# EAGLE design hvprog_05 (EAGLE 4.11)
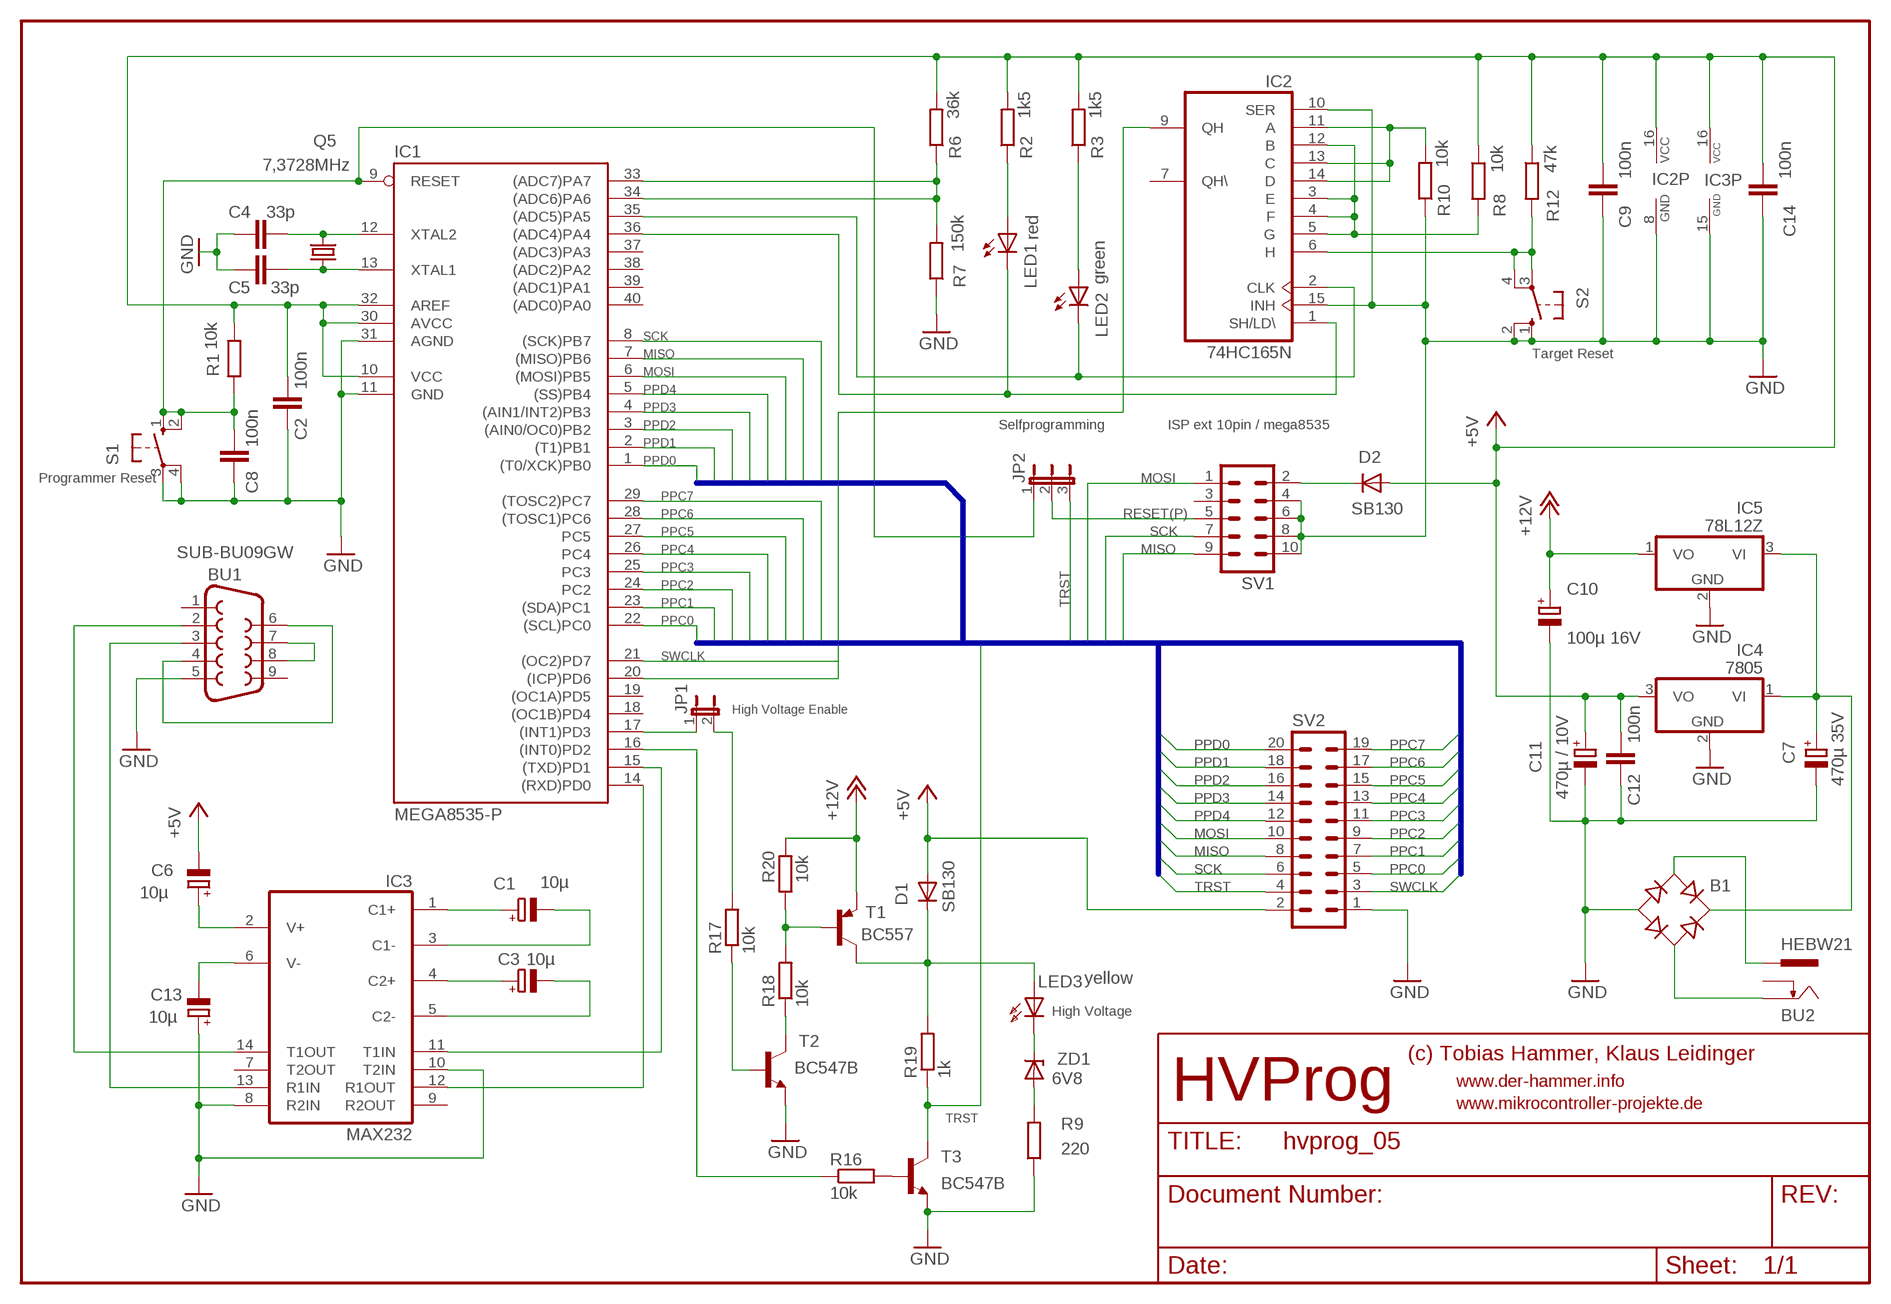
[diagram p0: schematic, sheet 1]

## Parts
B1  RB1A  [RB1A]
BU1  SUB-BU09GW  SUBD-F9WD-SUB-BU09GW  [SUBD-F9]
BU2  HEBW21  [HEBW21]
C1  10µ  CPOL-EUE1.8-4  [E1,8-4]
C2  100n  C-EU025-024X044  [C025-024X044]
C3  10µ  CPOL-EUE1.8-4  [E1,8-4]
C4  33p  C-EUC0805  [C0805]
C5  33p  C-EUC0805  [C0805]
C6  10µ  CPOL-EUE1.8-4  [E1,8-4]
C7  470µ 35V  CPOL-EUE5-10.5  [E5-10,5]
C8  100n  C-EU025-024X044  [C025-024X044]
C9  100n  C-EU025-024X044  [C025-024X044]
C10  100µ 16V  CPOL-EUE2.5-7  [E2,5-7]
C11  470µ / 10V  CPOL-EUE2.5-7  [E2,5-7]
C12  100n  C-EU025-024X044  [C025-024X044]
C13  10µ  CPOL-EUE1.8-4  [E1,8-4]
C14  100n  C-EU025-024X044  [C025-024X044]
D1  SB130  DIODE-D-2.5  [D-2.5]
D2  SB130  1N41485MM  [D-5]
IC1  MEGA8535-P  [DIL40]
IC2  74HC165N  [DIL16]
IC3  MAX232  [DIL16]
IC4  7805  78KL  [TO220H]
IC5  78L12Z  [TO92]
JP1  JP1E  [JP1]
JP2  JP2E  [JP2]
LED1  red  LED3MM  [LED3MM]
LED2  green  LED3MM  [LED3MM]
LED3  yellow  LED3MM  [LED3MM]
Q5  7,3728MHz  CRYTALHC49U-V  [HC49U-V]
R1  10k  R-EU_0204/7  [0204/7]
R2  1k5  R-EU_0204/7  [0204/7]
R3  1k5  R-EU_0204/7  [0204/7]
R6  36k  R-EU_0204/7  [0204/7]
R7  150k  R-EU_0204/7  [0204/7]
R8  10k  R-EU_0204/7  [0204/7]
R9  220  R-EU_0204/7  [0204/7]
R10  10k  R-EU_0204/7  [0204/7]
R12  47k  R-EU_0204/7  [0204/7]
R16  10k  R-EU_0204/7  [0204/7]
R17  10k  R-EU_0204/7  [0204/7]
R18  10k  R-EU_0204/7  [0204/7]
R19  1k  R-EU_0204/7  [0204/7]
R20  10k  R-EU_0204/7  [0204/7]
S1  10-XX  [B3F-10XX]
S2  10-XX  [B3F-10XX]
SV1  ML10L  [ML10L]
SV2  ML20L  [ML20L]
T1  BC557  [TO92]
T2  BC547B  [TO92]
T3  BC547B  [TO92]
ZD1  6V8  ZENER-DIODEZD-7.5  [ZDIO-7.5]

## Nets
+5V: C2.2 C6.- C9.1 C11.+ C12.1 C14.1 D1.A D2.A IC1.10(VCC) IC1.30(AVCC) IC1.32(AREF) IC2.16(VCC) IC3.16(VCC) IC4.3(VO) R1.2 R2.2 R3.2 R6.2 R8.1 R12.1 SV2.2
+12V: C10.+ IC5.1(VO) R20.2 T1.1(E)
GND: B1.- BU1.5 C2.1 C4.1 C5.1 C7.- C8.1 C9.2 C10.- C11.- C12.2 C13.+ C14.2 IC1.11(GND) IC1.31(AGND) IC2.8(GND) IC2.10(SER) IC2.15(INH) IC3.8(R2IN) IC3.10(T2IN) IC3.15(GND) IC4.2(GND) IC5.2(GND) R7.1 R9.1 R10.1 S1.3(P) S1.4(P1) S2.1(S) S2.2(S1) SV1.4 SV1.6 SV1.8 SV1.10 SV2.1 T2.1(E) T3.1(E)
MISO: IC1.7((MISO)PB6) SV1.9 SV2.8
MOSI: IC1.6((MOSI)PB5) SV1.1 SV2.10
N: IC1.36((ADC4)PA4) IC2.1(SH/LD\) LED1.K(C)
N$1: C4.2 IC1.12(XTAL2) Q5.2
N$2: C5.2 IC1.13(XTAL1) Q5.1
N$3: C8.2 IC1.9(RESET) JP2.1 R1.1 S1.1(S) S1.2(S1)
N$4: LED1.A R2.1
N$5: LED2.A R3.1
N$6: IC1.20((ICP)PD6) IC2.9(QH)
N$7: IC2.11(A) IC2.13(C) IC2.14(D) R10.2
N$8: IC1.35((ADC5)PA5) IC2.2(CLK) LED2.K(C)
N$9: IC1.33((ADC7)PA7) IC1.34((ADC6)PA6) R6.1 R7.2
N$10: BU1.7 BU1.8
N$11: IC1.16((INT0)PD2) R16.1
N$12: IC2.3(E) IC2.4(F) IC2.5(G) IC2.12(B) R8.2
N$13: R16.2 T3.2(B)
N$14: C1.+ IC3.1(C1+)
N$15: C1.- IC3.3(C1-)
N$16: C3.+ IC3.4(C2+)
N$17: C3.- IC3.5(C2-)
N$18: C13.- IC3.6(V-)
N$19: C6.+ IC3.2(V+)
N$20: IC2.6(H) R12.2 S2.3(P) S2.4(P1)
N$21: B1.+ C7.+ IC4.1(VI) IC5.3(VI)
N$22: B1.AC1 BU2.P$S(S)
N$23: B1.AC2 BU2.P$R(R)
N$24: LED3.K(C) ZD1.C
N$25: BU1.2 IC3.14(T1OUT)
N$26: BU1.3 IC3.13(R1IN)
N$27: IC1.14((RXD)PD0) IC3.12(R1OUT)
N$28: IC1.15((TXD)PD1) IC3.11(T1IN)
N$29: IC1.17((INT1)PD3) JP1.1
N$30: JP1.2 R17.2
N$31: R9.2 ZD1.A
N$32: BU1.4 BU1.6
N$33: D2.C SV1.2
N$34: D1.C LED3.A R19.2 T1.3(C)
N$35: R17.1 T2.2(B)
N$36: R18.1 T2.3(C)
N$38: R18.2 R20.1 T1.2(B)
PPC0: IC1.22((SCL)PC0) SV2.5
PPC1: IC1.23((SDA)PC1) SV2.7
PPC2: IC1.24(PC2) SV2.9
PPC3: IC1.25(PC3) SV2.11
PPC4: IC1.26(PC4) SV2.13
PPC5: IC1.27(PC5) SV2.15
PPC6: IC1.28((TOSC1)PC6) SV2.17
PPC7: IC1.29((TOSC2)PC7) SV2.19
PPD0: IC1.1((T0/XCK)PB0) SV2.20
PPD1: IC1.2((T1)PB1) SV2.18
PPD2: IC1.3((AIN0/OC0)PB2) SV2.16
PPD3: IC1.4((AIN1/INT2)PB3) SV2.14
PPD4: IC1.5((SS)PB4) SV2.12
RESET(P): JP2.2 SV1.5
SCK: IC1.8((SCK)PB7) SV1.7 SV2.6
SWCLK: IC1.21((OC2)PD7) SV2.3
TRST: JP2.3 R19.1 SV2.4 T3.3(C)
Unconnected: BU1.1 BU1.9 BU2.P$RS(RS) IC1.18((OC1B)PD4) IC1.19((OC1A)PD5) IC1.37((ADC3)PA3) IC1.38((ADC2)PA2) IC1.39((ADC1)PA1) IC1.40((ADC0)PA0) IC2.7(QH\) IC3.7(T2OUT) IC3.9(R2OUT) SV1.3

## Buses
B$2

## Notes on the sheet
- Target Reset
- Selfprogramming | ISP ext 10pin / mega8535
- Programmer Reset
- High Voltage Enable
- High Voltage
- (c) Tobias Hammer, Klaus Leidinger
- www.der-hammer.info
- HVProg
- www.mikrocontroller-projekte.de

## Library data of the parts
B1 = rectifier:RB1A: RECTIFIER 1 A
BU1 = mikrocontroller-projekte:SUBD-F9W
BU2 = mikrocontroller-projekte:HEBW21: Hohlstecker Winkelbuchse Reichelt HEBW21/25
C1 C3 C6 = rcl:CPOL-EU: POLARIZED CAPACITOR, European symbol
C2 C4 C5 C8 C9 C14 = rcl:C-EU: CAPACITOR, European symbol
C7 C10 C11 C13 = rc-elektronik:CPOL-EU: POLARIZED CAPACITOR, European symbol
C12 = rc-elektronik:C-EU: CAPACITOR, European symbol
D1 = diode:DIODE-: DIODE
D2 = diode:1N4148: DIODE
IC1 = avr:MEGA8535-P: MICROCONTROLLER 8 Kbytes FLASH 512 bytes SRAM 512 bytes EEPROM USART 8-channel 10 bit ADC
IC2 = 74xx-eu:74*165: 8-bit parallel load SHIFT REGISTER
IC3 = maxim:MAX232: RS232 TRANSEIVER
IC4 IC5 = rc-elektronik:78*: Positive VOLTAGE REGULATOR
JP1 = jumper:JP1E: JUMPER
JP2 = jumper:JP2E: JUMPER
LED1 LED2 = led:LED: LED
LED3 = rc-elektronik:LED: LED
Q5 = crystal:CRYTAL: CRYSTAL
R1-R3 R6-R10 R12 R16-R20 = rcl:R-EU_: RESISTOR, European symbol
S1 S2 = switch-omron:10-XX: OMRON SWITCH
SV1 = con-harting-ml:ML10: HARTING
SV2 = con-harting-ml:ML20: HARTING
T1 = transistor-pnp:BC557: PNP Transistor
T2 T3 = transistor-npn:BC547*: NPN Transistor
ZD1 = diode:ZENER-DIODE: Z-Diode

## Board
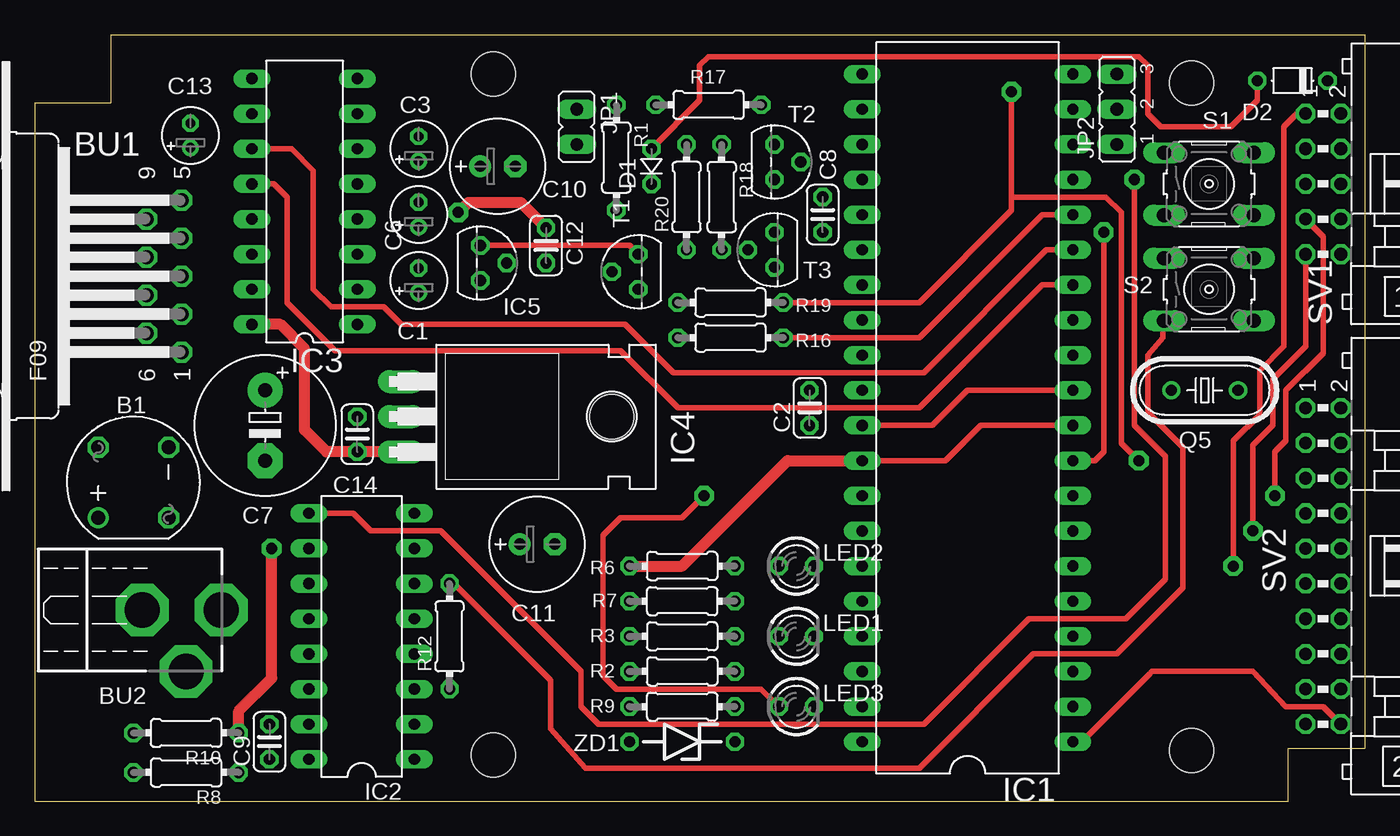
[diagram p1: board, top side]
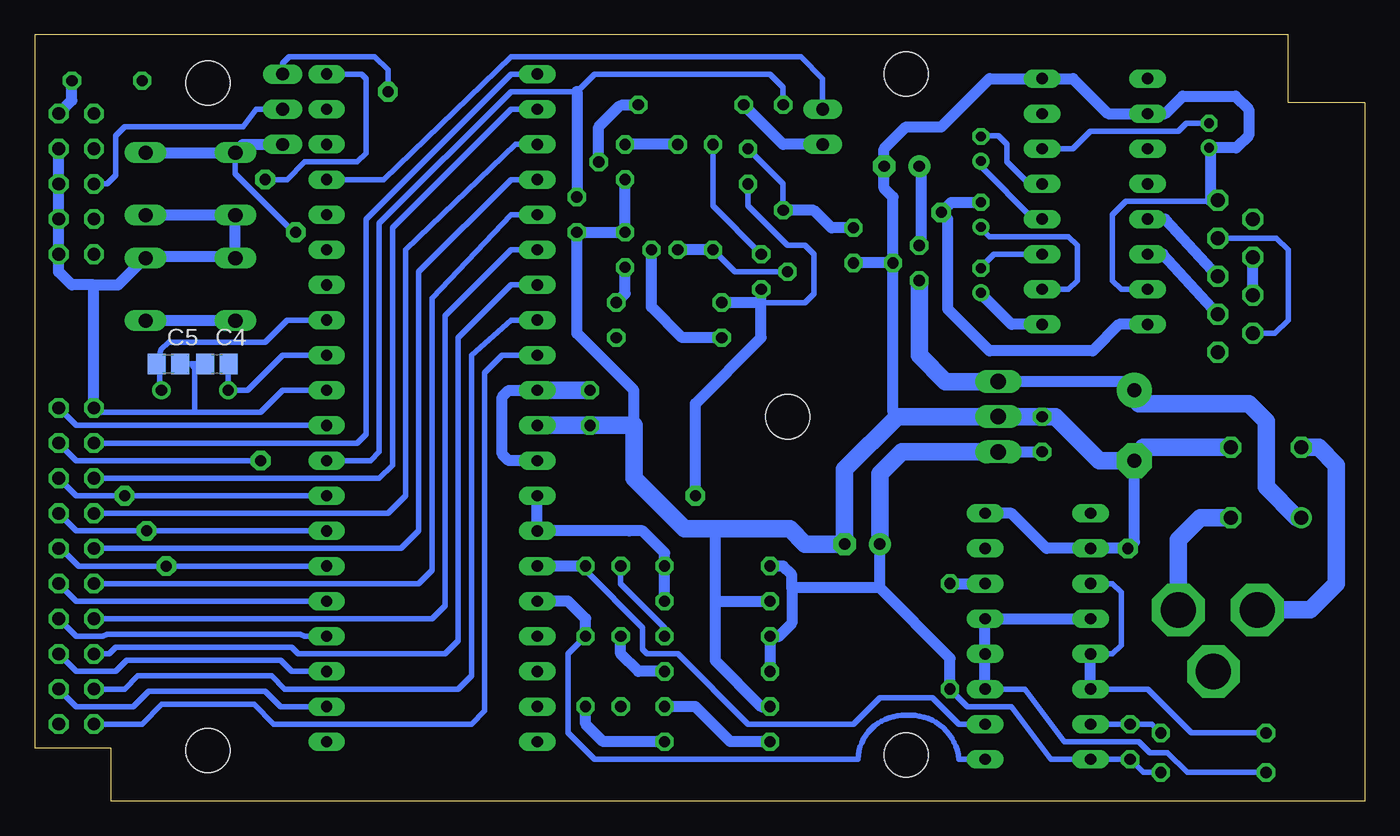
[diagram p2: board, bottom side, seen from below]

Size 96.2 x 55.4 mm. Coordinates in mm from the lower left corner, seen from the top.
Outline: 90.65,0 90.65,3.81 96.2,3.81 96.2,55.4 5.56,55.4 5.56,50.48 0,50.48 0,0 90.65,0
Copper layers (1*16): Top 0.035mm / dielectric 1.5mm / Bottom 0.035mm
Design rules "default": minimum track width 10mil, minimum drill 24mil, track to track 8mil, track to pad 8mil, pad to pad 8mil, via to via 8mil, smd to smd 8mil, copper to edge 40mil, drill to drill 8mil, minimum pad ring 10mil, minimum via ring 8mil, stop-mask expansion 4mil, vias tented up to drill 0mil, thermal gap 10mil
Holes 3.2 mm at 33.18,52.55 33.18,3.33 83.66,3.65 83.66,51.91 41.75,27.78

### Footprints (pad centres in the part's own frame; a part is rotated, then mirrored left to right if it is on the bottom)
RB1A = drill 1.016 round: + -2.54,2.54 | drill 1.016 octagon: - 2.54,-2.54; AC1 2.54,2.54; AC2 -2.54,-2.54
SUBD-F9 = drill 1.016 octagon: 1 -5.486,-10.16; 2 -2.743,-10.16; 3 0,-10.16; 4 2.743,-10.16; 5 5.486,-10.16; 6 -4.115,-7.62; 7 -1.372,-7.62; 8 1.372,-7.62; 9 4.115,-7.62
HEBW21 = drill 2.54 pad 3.81 octagon: P$R 0,3.175; P$RS 4.445,0.635; P$S 0,-2.54
E1,8-4 = drill 0.711 pad 1.168 round: + -0.889,0 | drill 0.711 pad 1.168 octagon: - 0.889,0
C025-024X044 = drill 0.813 octagon: 1 -1.27,0; 2 1.27,0
C0805 = smd 1.3 x 1.5: 1 -0.85,0; 2 0.85,0
E5-10,5 = drill 1.016 pad 2.54 round: + -2.54,0 | drill 1.016 pad 2.54 octagon: - 2.54,0
E2,5-7 = drill 0.813 pad 1.6 round: + -1.27,0 | drill 0.813 pad 1.6 octagon: - 1.27,0
D-2.5 = drill 0.813 octagon: A 1.27,0; C -1.27,0
D-5 = drill 0.813 octagon: A 2.54,0; C -2.54,0
DIL40 = drill 0.813 long: 1 -24.13,-7.62; 2 -21.59,-7.62; 3 -19.05,-7.62; 4 -16.51,-7.62; 5 -13.97,-7.62; 6 -11.43,-7.62; 7 -8.89,-7.62; 8 -6.35,-7.62; 9 -3.81,-7.62; 10 -1.27,-7.62; 11 1.27,-7.62; 12 3.81,-7.62; 13 6.35,-7.62; 14 8.89,-7.62; 15 11.43,-7.62; 16 13.97,-7.62; 17 16.51,-7.62; 18 19.05,-7.62; 19 21.59,-7.62; 20 24.13,-7.62; 21 24.13,7.62; 22 21.59,7.62; 23 19.05,7.62; 24 16.51,7.62; 25 13.97,7.62; 26 11.43,7.62; 27 8.89,7.62; 28 6.35,7.62; 29 3.81,7.62; 30 1.27,7.62; 31 -1.27,7.62; 32 -3.81,7.62; 33 -6.35,7.62; 34 -8.89,7.62; 35 -11.43,7.62; 36 -13.97,7.62; 37 -16.51,7.62; 38 -19.05,7.62; 39 -21.59,7.62; 40 -24.13,7.62
DIL16 = drill 0.813 long: 1 -8.89,-3.81; 2 -6.35,-3.81; 3 -3.81,-3.81; 4 -1.27,-3.81; 5 1.27,-3.81; 6 3.81,-3.81; 7 6.35,-3.81; 8 8.89,-3.81; 9 8.89,3.81; 10 6.35,3.81; 11 3.81,3.81; 12 1.27,3.81; 13 -1.27,3.81; 14 -3.81,3.81; 15 -6.35,3.81; 16 -8.89,3.81
TO220H = drill 1.118 long: 1 -2.54,-10.16; 2 0,-10.16; 3 2.54,-10.16
TO92 = drill 0.813 octagon: 1 -1.27,0; 2 0,1.905; 3 1.27,0
JP1 = drill 0.914 long: 1 0,-1.27; 2 0,1.27
JP2 = drill 0.914 long: 1 -2.54,0; 2 0,0; 3 2.54,0
LED3MM = drill 0.813 octagon: A -1.27,0; K 1.27,0
HC49U-V = drill 0.813 round: 1 -2.413,0; 2 2.413,0
0204/7 = drill 0.813 octagon: 1 -3.81,0; 2 3.81,0
B3F-10XX = drill 1.016 long: 1 -3.251,2.261; 2 3.251,2.261; 3 -3.251,-2.261; 4 3.251,-2.261
ML10L = drill 0.914 octagon: 1 -5.08,-1.27; 2 -5.08,1.27; 3 -2.54,-1.27; 4 -2.54,1.27; 5 0,-1.27; 6 0,1.27; 7 2.54,-1.27; 8 2.54,1.27; 9 5.08,-1.27; 10 5.08,1.27
ML20L = drill 0.914 octagon: 1 -11.43,-1.27; 2 -11.43,1.27; 3 -8.89,-1.27; 4 -8.89,1.27; 5 -6.35,-1.27; 6 -6.35,1.27; 7 -3.81,-1.27; 8 -3.81,1.27; 9 -1.27,-1.27; 10 -1.27,1.27; 11 1.27,-1.27; 12 1.27,1.27; 13 3.81,-1.27; 14 3.81,1.27; 15 6.35,-1.27; 16 6.35,1.27; 17 8.89,-1.27; 18 8.89,1.27; 19 11.43,-1.27; 20 11.43,1.27
TO92' = drill 0.813 octagon: 1 1.27,0; 2 0,1.905; 3 -1.27,0
ZDIO-7.5 = drill 0.813 octagon: A 3.81,0; C -3.81,0

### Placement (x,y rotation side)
B1  7.14,23.02 90 top
BU1  0.48,37.94 90 top
BU2  10.32,13.81 270 top
C1  27.78,37.62 90 top
C2  56.04,28.42 90 top
C3  27.78,47.15 90 top
C4  83.03,31.59 0 bottom
C5  86.52,31.59 180 bottom
C6  27.78,42.39 90 top
C7  16.67,27.15 270 top
C8  56.99,42.39 90 top
C9  16.99,4.29 90 top
C10  33.5,45.88 0 top
C11  36.35,18.57 0 top
C12  36.99,40.16 270 top
C13  11.27,48.1 90 top
C14  23.34,26.51 90 top
D1  44.61,45.88 90 top
D2  90.96,52.07 180 top
IC1  67.47,28.42 90 top
IC2  23.65,11.91 90 top
IC3  19.53,43.34 90 top
IC4  36.67,27.78 270 top
IC5  32.23,38.89 270 top
JP1  39.21,48.74 180 top
JP2  78.26,50.01 90 top
LED1  55.09,11.91 0 top
LED2  55.09,16.99 0 top
LED3  55.09,6.83 0 top
Q5  84.61,29.69 180 top
R1  42.07,46.51 270 top
R2  46.83,9.37 180 top
R3  46.83,11.91 180 top
R6  46.83,16.99 180 top
R7  46.83,14.45 0 top
R8  10.95,2.06 180 top
R9  46.83,6.83 0 top
R10  10.95,4.92 180 top
R12  30,11.91 90 top
R16  50.32,33.5 180 top
R17  48.74,50.32 180 top
R18  49.69,43.66 270 top
R19  50.32,36.04 180 top
R20  47.15,43.66 90 top
S1  84.93,44.61 0 top
S2  84.93,36.99 0 top
SV1  93.19,44.61 270 top
SV2  93.19,16.99 270 top
T1  BC557  [TO92']  43.66,38.26 90 top
T2  BC547B  [TO92']  53.5,46.2 270 top
T3  BC547B  [TO92']  53.5,39.85 90 top
ZD1  46.83,4.29 180 top

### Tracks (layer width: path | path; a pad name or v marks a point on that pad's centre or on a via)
+5V  (via drill 0.8 pad 1.42)
  Top 0.406: IC1.10 68.42,27.15 65.88,24.61 IC1.32 | D1.A 48.1,50.64 48.1,53.18 48.74,53.82 79.85,53.82 80.49,53.18 80.49,49.69 81.44,48.74 86.52,48.74 88.42,50.64 D2.A
  Top 0.813: IC3.16 17.78,34.45 19.53,32.7 19.53,26.83 21.11,25.24 IC4.3 | C12.1 35.15,43.27 31.37,43.27 v30.64,42.55 | R6.2 46.83,16.99 54.45,24.61 IC1.32 | IC1.32 | IC4.3 | v30.64,42.55 | v30.64,42.55
  Bottom 0.406: R12.1 28.73,6.83 25.56,6.83 22.7,3.02 IC2.16 C9.1 16.03,2.06 R8.1 | IC1.10 93.19,27.15 SV2.2 | R1.2 42.07,44.61 D1.A
  Bottom 0.813: R2.2 R3.2 42.39,11.91 41.43,12.86 41.43,15.4 | 35.08,15.4 C11.+ | 35.08,15.4 41.43,15.4 | 41.43,15.4 41.43,16.35 42.07,16.99 R6.2 | R12.1 30,10.32 35.08,15.4 | C12.1 38.58,41.43 39.85,42.7 R1.2 | IC3.16 15.56,34.45 17.78,34.45 19.68,32.54 27.15,32.54 30.16,35.56 30.16,42.07 v30.64,42.55 | IC1.30 61.91,29.69 62.39,29.21 62.39,25.08 61.91,24.61 60.01,24.61 59.85,24.45 IC1.32 | IC4.3 26.67,25.24 | IC4.3 | C14.1 | IC4.3 C14.1 | v30.64,42.55 | C6.- 29.91,43.27 v30.64,42.55
  Bottom 1.27: IC1.30 C2.2 | IC4.3 33.5,25.24 35.08,23.65 C11.+
+12V
  Top 0.406: T1.1 43.02,40.16 IC5.1 | IC5.1
  Bottom 0.406: T1.1 47.15,43.02 R20.2
  Bottom 0.813: 32.07,40.01 | IC5.1 32.07,40.01 | C10.+ 32.07,45.72 32.07,40.01
GND  (via drill 0.8 pad 1.42)
  Top 0.406: IC1.11 67.47,29.69 64.93,27.15 IC1.31
  Top 0.813: R10.1 14.76,6.51 17.14,8.89 v17.14,18.26
  Bottom 0.406: S2.2 88.06,39.37 | 81.72,39.25 81.68,39.29 | 81.72,39.25 81.76,39.21 81.91,39.37 | 81.72,39.25 S2.1 | IC1.11 78.26,29.69 79.85,28.1 84.61,28.1 | R10.1 15.4,5.56 C9.2 IC2.15 | 84.61,28.1 91.6,28.1 SV2.1 | C4.1 C5.1 84.93,31.59 84.61,31.27 84.61,28.1 | IC3.15 17.62,36.99 18.26,37.62 18.26,42.39 17.3,43.34 11.27,43.34 11.18,43.43 BU1.5 | C13.+ 11.27,47.15 11.18,47.06 | 16.03,24.92 16.03,25.56 | 33.81,27.78 34.13,28.1
  Bottom 0.813: T2.1 T3.1 C8.1 56.99,33.81 52.86,29.69 52.86,26.99 | SV1.4 SV1.6 SV1.8 SV1.10 94.46,38.26 93.5,37.31 91.92,37.31 | 81.68,39.29 S1.3 81.64,42.35 | 88.06,39.37 81.91,39.37 | R9.1 43.66,6.83 46.99,10.16 46.99,14.45 | 11.18,47.06 11.18,43.43 | C13.+ 9.3,47.21 8.41,48.1 8.41,50.01 9.37,50.96 13.18,50.96 14.45,49.69 IC3.10 18.57,49.69 21.11,52.23 IC3.8 27.15,52.23 30.64,48.74 33.18,48.74 34.77,47.15 C10.- 34.77,44.29 34.13,43.66 IC5.2 | 16.03,24.92 16.35,24.29 C7.- | IC2.8 25.56,20.8 23.02,18.26 IC2.10 v17.14,18.26 | IC5.2 C12.2 | 34.13,28.1 IC5.2 | 42.86,14.45 R7.1 | 46.99,14.45 42.86,14.45 | 42.86,14.45 | 46.99,19.68 46.99,14.45 | 81.64,42.35 S1.4 | 81.64,42.35 81.6,42.39 | S2.2 88.23,39.25 90.17,37.31 91.92,37.31 | SV2.1 91.92,37.31 | v17.14,18.26 | C7.- | v17.14,18.26 16.67,18.73 C7.-
  Bottom 1.27: C2.1 IC1.31 | 16.03,25.56 B1.- | C7.- 19.21,24.61 22.38,27.78 C14.2 IC4.2 33.81,27.78 37.62,23.97 C11.- 40.48,18.57 41.59,19.68 46.99,19.68 49.21,19.68 52.86,23.34 52.86,26.99 52.86,27.15 C2.1 | C2.1
MISO  (via drill 0.8 pad 1.42)
  Top 0.406: SV1.9 91.92,32.86 89.53,30.48 89.53,27.15 88.11,25.72 v88.11,19.53
  Bottom 0.406: IC1.7 | IC1.7 v88.11,19.53 93.19,19.53 SV2.8
MOSI  (via drill 0.8 pad 1.42)
  Top 0.406: SV1.1 91.28,49.69 90.33,48.74 90.33,32.86 88.58,31.11 88.58,27.94 86.68,26.04 v86.68,16.99
  Bottom 0.406: IC1.6 | IC1.6 88.26,16.99 | SV2.10 94.3,18.26 93.03,16.99 88.26,16.99 | 88.26,16.99 v86.68,16.99
N
  Bottom 0.406: 56.36,11.59 LED1.K 57.63,10.64 57.63,4.92 55.72,3.02 36.67,3.02 arc90 33.18,6.19 arc90 29.37,3.02 IC2.1
  Bottom 0.813: IC1.36 57.63,14.45 56.36,13.18 LED1.K
N$1
  Bottom 0.406: IC1.12 78.26,32.23 80.8,29.69 Q5.2 82.2,31.46 82.07,31.59 C4.2
N$2
  Bottom 0.406: IC1.13 77.95,34.77 79.53,33.18 86.52,33.18 87.05,32.65 C5.2 87.15,31.59 87.15,29.69 Q5.1
N$3  (via drill 0.8 pad 1.42)
  Top 0.406: v77.31,41.12 77.31,25.24 76.68,24.61 IC1.9
  Bottom 0.406: IC1.9 71.91,24.61 71.28,25.24 71.28,41.75 61.75,51.28 56.99,51.28 55.72,52.55 43.02,52.55 42.07,51.59 R1.1 | 81.76,46.83 81.72,46.87 S1.1 81.68,45.33 77.47,41.12 v77.31,41.12 | 88.11,46.83 88.14,46.87 S1.2
  Bottom 0.813: JP2.1 81.12,47.47 81.72,46.87 | 81.76,46.83 88.11,46.83 | 56.99,51.28 C8.2
N$4
  Bottom 0.813: LED1.A 53.82,10.64 52.55,9.37 R2.1
N$5
  Bottom 0.406: LED2.A 53.82,15.72 50.64,12.54 R3.1
N$6  (via drill 0.8 pad 1.42)
  Top 0.406: v79.53,44.93 79.53,27.15 81.76,24.92 81.76,23.97 81.76,22.7 81.76,16.03 78.9,13.18 71.91,13.18 64.29,5.56 40.8,5.56 39.53,6.83 39.53,9.37 29.37,19.53 24.29,19.53 23.02,20.8 IC2.9
  Bottom 0.406: IC1.20 72.55,52.55 72.23,52.23 72.23,46.83 72.87,46.2 76.68,46.2 77.95,44.93 v79.53,44.93
N$7
  Bottom 0.406: R10.2 12.54,4.92 15.72,8.1 IC2.14 | IC2.11 18.26,15.72 17.62,15.08 17.62,11.27 18.26,10.64 IC2.13
  Bottom 0.813: IC2.14 IC2.13
N$8
  Bottom 0.406: LED2.K 56.36,16.67 52.23,12.54 52.23,10.95 51.91,10.64 49.69,10.64 44.61,5.56 36.99,5.56 35.08,7.46 31.27,7.46 29.37,5.56 IC2.2
  Bottom 0.813: LED2.K IC1.35
N$9
  Bottom 0.406: R6.1 50.96,16.99
  Bottom 0.813: R7.2 R6.1 50.64,17.94 52.23,19.53 53.18,19.53 IC1.34 IC1.33
N$10
  Bottom 0.813: BU1.7 BU1.8
N$11
  Top 0.406: R16.1 63.98,33.5 72.87,42.39 IC1.16
N$12
  Bottom 0.406: R8.2 12.86,2.06 14.29,3.49 15.56,3.49 16.35,4.29 21.75,4.29 24.61,8.1 IC2.3
  Bottom 0.813: IC2.3 IC2.4 IC2.5 IC2.12
N$13
  Bottom 0.813: R16.2 49.37,33.5 51.59,35.72 T3.2
N$14
  Bottom 0.406: 27.78,36.67 C1.+
  Bottom 0.813: IC3.1 25.56,34.45 27.78,36.67
N$15
  Bottom 0.406: C1.- 27.78,38.58 26.83,39.53 IC3.3
N$16
  Bottom 0.406: C3.+ 27.78,45.88 23.97,42.07 IC3.4
N$17
  Bottom 0.406: IC3.5 24.29,44.61 25.88,46.2 25.88,47.47 26.51,48.1 27.46,48.1 27.53,48.04 C3.-
N$18
  Bottom 0.406: C13.- 12.92,48.99 13.49,48.42 19.84,48.42 21.11,47.15 IC3.6
N$19
  Bottom 0.406: IC3.2 21.43,36.99 20.8,37.62 20.8,40.16 21.43,40.8 27.15,40.8 27.78,41.43 C6.+
N$20
  Top 0.406: R12.2 30,16.03 37.31,8.73 37.31,5.24 39.85,2.38 63.98,2.38 72.23,10.64 78.26,10.64 83.03,15.4 83.03,25.56 80.49,28.1 80.49,32.23 81.6,33.5 81.6,34.77
  Top 0.813: 81.6,34.77 81.64,34.73 S2.3
  Bottom 0.813: R12.2 IC2.6 | S2.4 88.14,34.73 88.11,34.77 88.07,34.73 S2.3
N$21
  Bottom 0.406: B1.+ 4.92,20.48 | C7.+ 16.67,29.37 16.35,29.05 16.35,28.73
  Bottom 0.813: C7.+ 17.3,30.32 IC4.1
  Bottom 1.27: 4.92,20.48 7.14,22.7 7.14,27.46 8.41,28.73 16.35,28.73 | IC4.1 30.32,30.32 32.23,32.23 IC5.3
N$22
  Bottom 0.406: BU2.P$S 7.78,13.49 7.46,13.81
  Bottom 1.27: B1.AC1 3.33,25.56 2.06,24.29 2.06,15.72 3.97,13.81 7.46,13.81
N$23
  Bottom 1.27: B1.AC2 11.91,20.48 13.49,18.89 BU2.P$R
N$24
  Bottom 0.813: ZD1.C 55.09,4.29 56.36,5.56 LED3.K | LED3.K
N$25
  Bottom 0.813: BU1.2 14.6,39.53 15.56,39.53 IC3.14
N$26
  Bottom 0.813: BU1.3 14.45,42.07 15.56,42.07 IC3.13
N$27
  Top 0.406: IC1.14 72.87,37.31 63.98,28.42 46.51,28.42 42.39,32.54 21.75,32.54 18.26,36.04 18.26,43.66 17.3,44.61 IC3.12
N$28
  Top 0.406: IC1.15 73.18,39.85 64.29,30.96 46.2,30.96 42.7,34.45 26.51,34.45 25.24,35.72 21.43,35.72 20.16,36.99 20.16,45.56 18.57,47.15 IC3.11
N$29
  Bottom 0.406: IC1.17 70.96,44.93 61.75,53.82 40.8,53.82 39.21,52.23 JP1.1
N$30
  Bottom 0.813: JP1.2 42.07,47.47 R17.2
N$31
  Bottom 0.813: ZD1.A 45.88,4.29 48.42,6.83 R9.2
N$32
  Bottom 0.406: BU1.4 6.39,40.68 5.56,39.85 5.56,34.77 6.51,33.81 7.94,33.81 7.95,33.83 BU1.6
N$33
  Bottom 0.813: D2.C 93.5,50.64 SV1.2
N$34  (via drill 0.8 pad 1.42)
  Top 0.406: v48.42,22.07 46.83,20.48 42.39,20.48 41.12,19.21 41.12,9.05 42.07,8.1 52.55,8.1 LED3.A
  Bottom 0.406: D1.C 44.61,43.02 41.75,40.16 40.48,40.16 39.85,39.53 39.85,36.67 40.48,36.04 43.66,36.04
  Bottom 0.813: 43.66,36.04 43.66,33.5 48.42,28.73 v48.42,22.07 | 43.66,36.04 T1.3 | 43.66,36.04 R19.2
N$35
  Bottom 0.406: 53.89,50.25 arc45 53.71,50.32
  Bottom 0.813: 53.71,50.32 R17.1 | 53.89,50.25 55.4,48.74 T2.2
N$36
  Bottom 0.813: R18.1 T2.3
N$38
  Bottom 0.406: T1.2 45.56,38.26 R20.1
  Bottom 0.813: R20.1 R18.2
PPC0
  Bottom 0.406: IC1.22 61.75,50.01 70.33,41.43 70.33,24.29 71.28,23.34 SV2.5
PPC1
  Bottom 0.406: IC1.23 61.44,47.47 69.37,39.85 69.37,22.07 70.64,20.8 SV2.7
PPC2
  Bottom 0.406: IC1.24 61.75,44.93 68.42,38.26 68.42,19.53 69.69,18.26 SV2.9
PPC3
  Bottom 0.406: IC1.25 61.75,42.39 67.47,36.35 67.47,16.67 68.42,15.72 SV2.11
PPC4
  Bottom 0.406: IC1.26 61.75,39.85 66.52,35.08 66.52,14.13 67.47,13.18 SV2.13
PPC5
  Bottom 0.406: IC1.27 61.75,37.31 65.56,33.5 65.56,11.59 66.52,10.64 77.15,10.64 77.63,11.11 90.33,11.11 90.8,10.64 SV2.15
PPC6
  Bottom 0.406: IC1.28 61.75,34.77 64.61,32.23 64.61,9.05 65.56,8.1 78.1,8.1 79.06,9.05 88.74,9.05 89.69,8.1 SV2.17
PPC7
  Bottom 0.406: IC1.29 62.39,32.23 63.66,30.96 63.66,6.51 64.61,5.56 78.9,5.56 80.33,6.99 86.99,6.99 88.42,5.56 SV2.19
PPD0
  Top 0.406: SV2.20 94.61,5.4 | SV2.20 | SV2.20 93.19,6.83 90.49,6.83 88.11,9.37 80.8,9.37 80.64,9.21 75.72,4.29 75.25,4.29 75.09,4.45 IC1.1
PPD1
  Bottom 0.406: SV2.18 93.19,6.83 89.06,6.83 87.95,7.94 79.53,7.94 78.42,6.83 IC1.2
PPD2
  Bottom 0.406: SV2.16 93.19,9.37 90.33,9.37 89.53,10.16 78.42,10.16 77.63,9.37 IC1.3
PPD3
  Bottom 0.406: SV2.14 93.19,11.91 91.28,11.91 90.96,12.06 76.99,12.06 76.68,11.91 IC1.4
PPD4
  Bottom 0.406: IC1.5 93.19,14.45 SV2.12
RESET(P)
  Bottom 0.406: JP2.2 80.17,50.01 81.12,48.74 89.69,48.74 90.33,48.1 90.33,45.24 90.96,44.61 SV1.5
SCK  (via drill 0.8 pad 1.42)
  Top 0.406: SV1.7 93.19,40.8 93.19,32.38 90.49,29.69 90.49,26.04 89.69,25.24 v89.69,22.07
  Bottom 0.406: SV2.6 | SV2.6 93.19,22.07 v89.69,22.07 90.49,22.07 IC1.8
SWCLK
  Bottom 0.406: IC1.21 61.75,52.55 72.23,42.07 72.23,26.51 72.87,25.88 SV2.3
TRST  (via drill 0.8 pad 1.42)
  Top 0.406: R19.1 63.98,36.04 70.64,42.7 70.64,43.66 | v79.85,24.61 78.58,25.88 78.58,42.55 77.47,43.66 70.64,43.66 | 70.64,43.66 v70.64,51.28
  Bottom 0.406: SV2.4 93.19,24.61 v79.85,24.61 | v70.64,51.28 70.64,52.86 71.6,53.82 77.79,53.82 78.26,53.34 JP2.3
  Bottom 0.813: T3.3 53.5,36.67 R19.1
